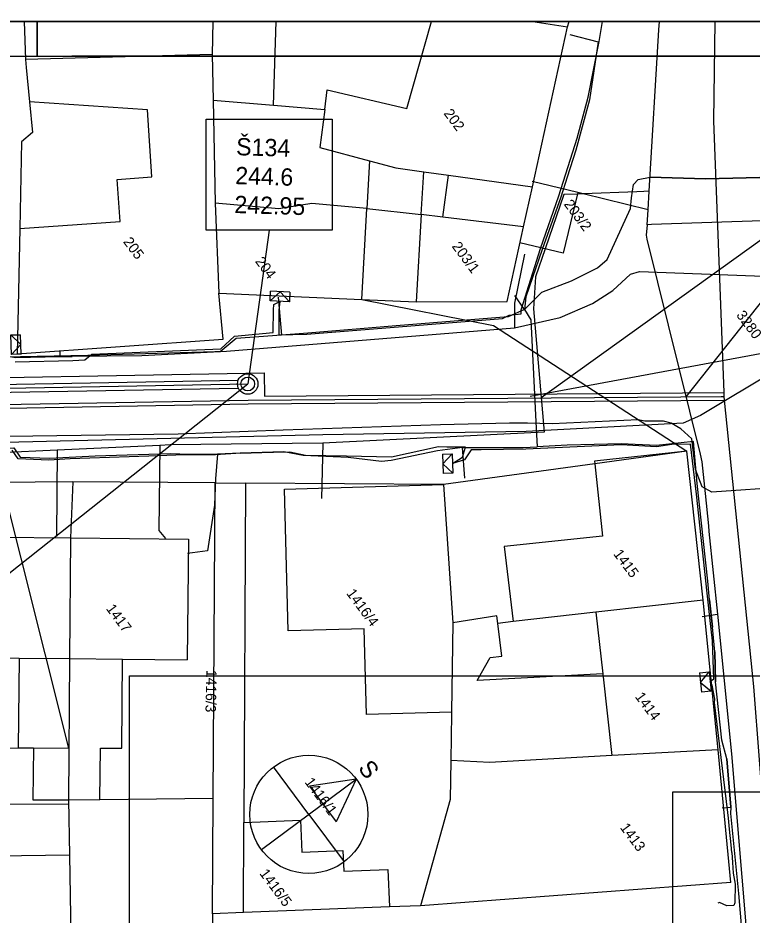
# Model space of a CAD drawing. Extents: x -601580 to 4, y -1204314 to 4.
# Drawn here: x -601370.3 to -601317.3, y -1203332.8 to -1203268.1 of the extents above; entities that cross this region are included whole.
import ezdxf

# ---------------------------------------------------------------- set-up
doc = ezdxf.new("R2010")
doc.units = 0
for name, color, linetype in [('00-EON NN', 7, 'Continuous'), ('00-EON VN', 7, 'Continuous'), ('00-INNOGY-NTL', 7, 'Continuous'), ('00-KN-HRANICE PARCEL', 7, 'Continuous'), ('00-KN-PARC. CISLA', 7, 'Continuous'), ('00-KN-VNITRNI KRESBA', 7, 'Continuous'), ('00-RAZÍTKO', 7, 'Continuous'), ('00-SITE KOM. KABEL', 7, 'Continuous'), ('00-VAK-KANAL-POTRUBI', 7, 'Continuous'), ('00-VAK-VODA-RAD IGIS', 7, 'Continuous'), ('01 KOTA', 7, 'Continuous'), ('11-REKONSTRUKCE  VYKOP', 7, 'Continuous'), ('11-REKONSTRUKCE KANALIZACE', 7, 'Continuous'), ('11-REKONSTRUKCE KANALIZACE OSA', 7, 'Continuous'), ('11-REKONSTRUKCE KANALIZACE POPIS', 7, 'Continuous'), ('11-REKONSTRUKCE VODOVOD', 7, 'Continuous'), ('11-REKONSTRUKCE VODOVOD POPIS', 7, 'Continuous'), ('Vrstva 26', 7, 'Continuous'), ('Vrstva 9', 7, 'Continuous')]:
    doc.layers.add(name, color=color, linetype=linetype)

# ---------------------------------------------------------------- blocks, each defined once
blk = doc.blocks.new('NN630')
at = {"layer": 'Vrstva 9'}
for points in [[(-3, -700), (-703, 0)], [(-703, -700), (-703, 0), (697, 0), (697, -700)], [(-3, -700), (697, 0)], [(-703, -700), (697, -700)]]:
    blk.add_lwpolyline(points, dxfattribs=at)

msp = doc.modelspace()

# ---------------------------------------------------------------- linework, layer by layer
for points in [[(-601368.935, -1203270.826), (-601368.935, -1203268.326), (-601473.985, -1203268.326), (-601473.985, -1203270.826)], [(-601368.935, -1203414.326), (-601368.935, -1203416.826), (-601263.884, -1203416.826), (-601263.884, -1203268.326), (-601368.935, -1203268.326), (-601368.935, -1203270.826)], [(-601366.435, -1203414.326), (-601266.384, -1203414.326), (-601266.384, -1203270.826), (-601366.435, -1203270.826)]]:
    msp.add_lwpolyline(points)
at = {"layer": '00-EON NN'}
for points in [[(-601370.525, -1203292.903), (-601366.381, -1203292.812), (-601365.494, -1203292.77), (-601364.997, -1203292.35), (-601355.673, -1203291.976), (-601354.686, -1203291.056), (-601351.897, -1203290.798), (-601351.885, -1203289.162), (-601351.854, -1203288.77), (-601351.434, -1203288.543), (-601351.486, -1203289.179), (-601351.498, -1203290.962), (-601349.472, -1203290.919), (-601335.35, -1203289.767), (-601334.874, -1203289.527), (-601333.996, -1203289.435), (-601334.002, -1203289.141), (-601332.604, -1203284.716), (-601331.269, -1203280.911), (-601329.955, -1203276.759), (-601329.152, -1203273.797), (-601328.355, -1203269.772), (-601328.118, -1203268.326)], [(-601320.354, -1203315.985), (-601320.091, -1203315.803), (-601320.181, -1203313.048), (-601320.343, -1203311.589), (-601320.56, -1203309.6), (-601321.326, -1203302.46), (-601321.764, -1203298.85), (-601323.127, -1203298.877), (-601324.226, -1203299.049), (-601326.763, -1203298.911), (-601333.67, -1203299.219), (-601336.88, -1203299.254)], [(-601339.353, -1203299.057), (-601339.966, -1203299.052), (-601343.369, -1203299.793), (-601346.599, -1203299.707), (-601349.562, -1203299.661), (-601350.71, -1203299.426), (-601354.23, -1203299.503), (-601356.07, -1203299.632), (-601358.929, -1203299.635), (-601360.893, -1203299.724), (-601366.566, -1203299.9), (-601368.091, -1203300.01), (-601370.311, -1203299.902), (-601370.749, -1203299.281)], [(-601336.88, -1203299.254), (-601337.616, -1203299.262), (-601338.095, -1203299.986), (-601338.956, -1203300.248), (-601338.221, -1203299.791), (-601338.009, -1203299.068), (-601339.353, -1203299.057)], [(-601320.027, -1203317.499), (-601320.012, -1203317.251), (-601320.215, -1203316.256), (-601320.354, -1203315.985)], [(-601318.779, -1203328.341), (-601318.825, -1203327.775), (-601318.942, -1203326.644), (-601319.021, -1203325.849), (-601319.078, -1203325.438), (-601320.027, -1203317.499)], [(-601318.779, -1203328.341), (-601318.726, -1203329.05), (-601318.698, -1203329.826), (-601318.544, -1203330.62), (-601318.559, -1203331.976), (-601318.639, -1203332.154), (-601319.138, -1203332.194), (-601319.667, -1203331.951), (-601319.799, -1203332)]]:
    msp.add_lwpolyline(points, dxfattribs=at)
at = {"layer": '00-EON VN'}
for points in [[(-601315.562, -1203268.326), (-601315.61, -1203274.198), (-601315.387, -1203285.467), (-601315.047, -1203290.112), (-601315.056, -1203292.512), (-601315.467, -1203293.437), (-601321.049, -1203296.77), (-601322.289, -1203297.339), (-601333.626, -1203297.94), (-601348.329, -1203298.17), (-601379.275, -1203298.932), (-601388.418, -1203299.122), (-601401.119, -1203299.449), (-601407.186, -1203299.441), (-601413.599, -1203299.611), (-601425.994, -1203301.007), (-601438.778, -1203302.641), (-601441.293, -1203303.148), (-601442.541, -1203303.128)], [(-601308.054, -1203364.739), (-601308.692, -1203358.556), (-601308.622, -1203357.458), (-601310.497, -1203339.547), (-601312.465, -1203319.363), (-601313.985, -1203302.433), (-601314.675, -1203301.923), (-601320.229, -1203302.31), (-601320.923, -1203301.928), (-601321.405, -1203300.692), (-601321.682, -1203298.456), (-601322.454, -1203297.735), (-601323.158, -1203297.323), (-601323.723, -1203297.182), (-601325.069, -1203297.198), (-601325.539, -1203297.085), (-601331.758, -1203297.38), (-601333.532, -1203297.34), (-601334.848, -1203297.345), (-601339.825, -1203297.452), (-601351.175, -1203297.832), (-601358.752, -1203298.126), (-601371.007, -1203298.293)]]:
    msp.add_lwpolyline(points, dxfattribs=at)
at = {"layer": '00-INNOGY-NTL'}
for p, q in [((-601329.907, -1203280.683), (-601333.213, -1203279.887)), ((-601367.49, -1203299.277), (-601367.557, -1203305.529)), ((-601320.927, -1203311.304), (-601319.828, -1203311.124))]:
    msp.add_line(p, q, dxfattribs=at)
for points in [[(-601324.893, -1203283.026), (-601324.829, -1203281.921), (-601324.746, -1203280.589), (-601324.05, -1203268.926), (-601324.016, -1203268.326)], [(-601329.907, -1203280.683), (-601330.969, -1203285.058), (-601334.081, -1203284.305)], [(-601325.633, -1203280.637), (-601329.527, -1203280.775), (-601329.937, -1203280.793), (-601330.922, -1203280.826), (-601332.265, -1203284.738), (-601332.959, -1203286.772), (-601333.107, -1203289.073), (-601332.331, -1203297.987)], [(-601324.829, -1203281.921), (-601329.527, -1203280.775), (-601329.907, -1203280.683)], [(-601324.746, -1203280.589), (-601325.137, -1203280.617), (-601325.633, -1203280.637)], [(-601316.599, -1203282.723), (-601324.58, -1203282.994), (-601324.893, -1203283.026), (-601324.966, -1203283.766), (-601324.924, -1203284.058), (-601321.063, -1203299.561), (-601320.961, -1203300.134), (-601320.707, -1203302.423), (-601320.48, -1203304.758), (-601320.438, -1203305.151), (-601319.828, -1203311.124), (-601318.804, -1203321.211), (-601316.942, -1203343.316)], [(-601332.331, -1203297.987), (-601348.309, -1203298.776), (-601359.342, -1203298.895), (-601360.084, -1203298.936), (-601367.49, -1203299.277), (-601371.643, -1203299.47), (-601372.283, -1203299.497), (-601387.135, -1203299.923), (-601391.708, -1203300.055), (-601393.151, -1203299.955), (-601393.463, -1203299.938), (-601394.572, -1203299.752), (-601396.304, -1203299.232), (-601396.572, -1203299.156), (-601396.715, -1203299.114), (-601406.965, -1203299.349), (-601407.169, -1203299.376), (-601414.127, -1203300.319), (-601427.425, -1203302.119), (-601427.687, -1203302.152)], [(-601360.084, -1203298.936), (-601360.159, -1203305.093), (-601359.669, -1203305.652)], [(-601348.309, -1203298.776), (-601348.423, -1203302.784)]]:
    msp.add_lwpolyline(points, dxfattribs=at)
at = {"layer": '00-KN-HRANICE PARCEL'}
for p, q in [((-601369.888, -1203268.326), (-601369.785, -1203271.067)), ((-601356.266, -1203268.326), (-601356.317, -1203270.722)), ((-601330.639, -1203268.724), (-601330.532, -1203268.326)), ((-601333.184, -1203280.277), (-601330.639, -1203268.724)), ((-601356.317, -1203270.722), (-601369.785, -1203271.067)), ((-601356.317, -1203270.722), (-601356.248, -1203274.02)), ((-601339.242, -1203279.431), (-601333.184, -1203280.277)), ((-601333.819, -1203283.164), (-601333.184, -1203280.277)), ((-601355.829, -1203287.957), (-601345.501, -1203288.398)), ((-601355.505, -1203291.278), (-601355.829, -1203287.957)), ((-601345.501, -1203288.398), (-601341.566, -1203288.566)), ((-601370.387, -1203292.336), (-601355.505, -1203291.278)), ((-601320.85, -1203310.115), (-601322.033, -1203299.361)), ((-601366.376, -1203301.564), (-601379.317, -1203301.68)), ((-601356.103, -1203301.647), (-601366.376, -1203301.564)), ((-601356.24, -1203324.415), (-601356.103, -1203301.647)), ((-601356.103, -1203301.647), (-601353.903, -1203301.658)), ((-601353.903, -1203301.658), (-601354.019, -1203326.166)), ((-601339.595, -1203301.773), (-601353.903, -1203301.658)), ((-601339.595, -1203301.773), (-601338.935, -1203311.757)), ((-601319.774, -1203320.91), (-601320.85, -1203310.115)), ((-601338.935, -1203311.757), (-601339.017, -1203318.207)), ((-601318.85, -1203330.511), (-601319.774, -1203320.91)), ((-601366.679, -1203324.529), (-601366.618, -1203328.52)), ((-601356.295, -1203332.763), (-601356.24, -1203324.415)), ((-601354.045, -1203332.674), (-601354.019, -1203326.166)), ((-601366.618, -1203328.52), (-601377.933, -1203328.711)), ((-601366.618, -1203328.52), (-601366.36, -1203342.861)), ((-601318.85, -1203330.511), (-601341.254, -1203332.172)), ((-601343.513, -1203332.266), (-601354.045, -1203332.674)), ((-601341.254, -1203332.172), (-601343.513, -1203332.266)), ((-601354.045, -1203332.674), (-601356.295, -1203332.763)), ((-601356.295, -1203332.763), (-601356.09, -1203342.1))]:
    msp.add_line(p, q, dxfattribs=at)
for points in [[(-601333.159, -1203268.326), (-601330.639, -1203268.724)], [(-601369.785, -1203271.067), (-601369.73, -1203271.661), (-601369.502, -1203274.133), (-601369.287, -1203276.352), (-601370.073, -1203277.022), (-601370.206, -1203283.285), (-601370.387, -1203292.336)], [(-601356.248, -1203274.02), (-601351.883, -1203274.38), (-601348.183, -1203274.684), (-601348.526, -1203277.443), (-601344.943, -1203278.395)], [(-601356.248, -1203274.02), (-601356.088, -1203281.449), (-601355.829, -1203287.957)], [(-601344.943, -1203278.395), (-601345.136, -1203281.826), (-601341.206, -1203282.271), (-601341.566, -1203288.566)], [(-601344.943, -1203278.395), (-601343.046, -1203278.904), (-601341.029, -1203279.188), (-601339.242, -1203279.431)], [(-601333.819, -1203283.164), (-601339.661, -1203282.457), (-601339.242, -1203279.431)], [(-601341.566, -1203288.566), (-601335.009, -1203288.556), (-601333.819, -1203283.164)], [(-601345.501, -1203288.398), (-601335.986, -1203290.277), (-601322.033, -1203299.361)], [(-601322.033, -1203299.361), (-601328.688, -1203300.278), (-601339.595, -1203301.773)], [(-601366.376, -1203301.564), (-601366.541, -1203305.622), (-601366.606, -1203314.325), (-601366.679, -1203324.529)], [(-601339.017, -1203318.207), (-601345.174, -1203318.368), (-601345.337, -1203312.175), (-601350.814, -1203312.33), (-601351.093, -1203302.088), (-601339.595, -1203301.773)], [(-601320.85, -1203310.115), (-601328.599, -1203310.984), (-601334.574, -1203311.659), (-601335.673, -1203311.789), (-601335.748, -1203311.235), (-601338.935, -1203311.757)], [(-601339.017, -1203318.207), (-601339.019, -1203318.321), (-601339.076, -1203321.7)], [(-601319.774, -1203320.91), (-601327.45, -1203321.34), (-601336.251, -1203321.832), (-601339.076, -1203321.7)], [(-601339.076, -1203321.7), (-601339.126, -1203324.502), (-601341.254, -1203332.172)], [(-601366.679, -1203324.529), (-601364.424, -1203324.512), (-601356.24, -1203324.415)], [(-601354.019, -1203326.166), (-601349.928, -1203326.006), (-601349.839, -1203328.307), (-601346.871, -1203328.196), (-601346.806, -1203329.692), (-601343.621, -1203329.57), (-601343.513, -1203332.266)]]:
    msp.add_lwpolyline(points, dxfattribs=at)
at = {"layer": '00-KN-VNITRNI KRESBA'}
for p, q in [((-601351.883, -1203274.38), (-601351.683, -1203268.326)), ((-601342.248, -1203274.626), (-601340.459, -1203268.326)), ((-601348.183, -1203274.684), (-601348.002, -1203273.267)), ((-601348.002, -1203273.267), (-601342.248, -1203274.626)), ((-601360.989, -1203274.713), (-601369.502, -1203274.133)), ((-601360.655, -1203279.559), (-601360.989, -1203274.713)), ((-601341.206, -1203282.271), (-601341.029, -1203279.188)), ((-601363.168, -1203279.73), (-601360.655, -1203279.559)), ((-601362.955, -1203282.785), (-601363.168, -1203279.73)), ((-601351.502, -1203281.856), (-601356.088, -1203281.449)), ((-601349.117, -1203281.48), (-601351.502, -1203281.856)), ((-601345.136, -1203281.826), (-601349.117, -1203281.48)), ((-601345.501, -1203288.398), (-601345.136, -1203281.826)), ((-601339.661, -1203282.457), (-601341.206, -1203282.271)), ((-601370.206, -1203283.285), (-601362.955, -1203282.785)), ((-601322.033, -1203299.361), (-601328.709, -1203300.082)), ((-601328.709, -1203300.082), (-601328.688, -1203300.278)), ((-601328.688, -1203300.278), (-601328.116, -1203305.495)), ((-601375.028, -1203305.546), (-601366.541, -1203305.622)), ((-601366.541, -1203305.622), (-601358.025, -1203305.702)), ((-601358.025, -1203305.702), (-601358.106, -1203314.418)), ((-601328.116, -1203305.495), (-601335.217, -1203306.245)), ((-601335.217, -1203306.245), (-601334.574, -1203311.659)), ((-601328.599, -1203310.984), (-601328.105, -1203315.425)), ((-601335.387, -1203314.155), (-601335.673, -1203311.789)), ((-601375.1, -1203314.241), (-601370.254, -1203314.293)), ((-601370.254, -1203314.293), (-601370.318, -1203320.767)), ((-601370.254, -1203314.293), (-601366.606, -1203314.325)), ((-601366.606, -1203314.325), (-601362.774, -1203314.371)), ((-601362.838, -1203320.794), (-601362.774, -1203314.371)), ((-601362.774, -1203314.371), (-601358.106, -1203314.418)), ((-601337.175, -1203315.906), (-601336.239, -1203314.264)), ((-601336.239, -1203314.264), (-601335.387, -1203314.155)), ((-601328.105, -1203315.425), (-601337.175, -1203315.906)), ((-601328.105, -1203315.425), (-601327.45, -1203321.34)), ((-601370.318, -1203320.767), (-601369.218, -1203320.773)), ((-601369.218, -1203320.773), (-601369.261, -1203324.54)), ((-601364.424, -1203324.512), (-601364.384, -1203320.809)), ((-601364.384, -1203320.809), (-601362.838, -1203320.794)), ((-601369.261, -1203324.54), (-601366.679, -1203324.529))]:
    msp.add_line(p, q, dxfattribs=at)
at = {"layer": '00-RAZÍTKO'}
for points in [[(-601579.036, -1203268.326), (-601263.884, -1203268.326), (-601263.884, -1203416.826), (-601579.036, -1203416.826)], [(-601576.536, -1203270.826), (-601266.384, -1203270.826), (-601266.384, -1203414.326), (-601576.536, -1203414.326)], [(-601266.384, -1203414.326), (-601362.277, -1203414.326), (-601362.277, -1203315.575), (-601266.384, -1203315.575)], [(-601323.044, -1203323.964), (-601269.935, -1203323.964), (-601269.935, -1203360.386), (-601323.044, -1203360.386)]]:
    msp.add_lwpolyline(points, close=True, dxfattribs=at)
at = {"layer": '00-SITE KOM. KABEL'}
for points in [[(-601465.666, -1203268.077), (-601465.45, -1203271.476), (-601465.203, -1203281.741), (-601464.718, -1203292.278), (-601464.228, -1203298.054), (-601463.764, -1203299.317), (-601461.865, -1203300.198), (-601444.628, -1203297.566), (-601422.377, -1203294.288), (-601417.815, -1203293.891), (-601412.74, -1203293.648), (-601407.783, -1203293.531), (-601395.711, -1203293.151), (-601385.448, -1203292.968), (-601371.384, -1203292.553), (-601365.297, -1203292.432), (-601355.273, -1203292.127), (-601334.483, -1203290.457)], [(-601330.47, -1203269.27), (-601328.426, -1203269.809)], [(-601328.426, -1203269.809), (-601329.065, -1203273.981), (-601330.041, -1203277.633), (-601330.679, -1203279.575), (-601331.12, -1203281.011), (-601332.487, -1203284.791), (-601333.664, -1203288.205), (-601333.756, -1203289.12)], [(-601328.426, -1203269.809), (-601329.065, -1203273.981)], [(-601326.04, -1203281.077), (-601325.887, -1203280.091), (-601325.55, -1203279.741), (-601324.673, -1203279.563), (-601320.689, -1203279.695), (-601315.769, -1203279.58), (-601314.58, -1203279.369)], [(-601330.679, -1203279.575), (-601331.12, -1203281.011)], [(-601315.769, -1203279.58), (-601320.689, -1203279.695), (-601324.673, -1203279.563)], [(-601333.756, -1203289.12), (-601332.514, -1203287.874), (-601330.35, -1203287.065), (-601328.481, -1203286.126), (-601327.79, -1203285.514), (-601326.104, -1203281.846), (-601326.04, -1203281.077)], [(-601331.12, -1203281.011), (-601332.487, -1203284.791)], [(-601333.744, -1203285.126), (-601334.476, -1203288.671), (-601334.483, -1203290.457)], [(-601334.483, -1203290.457), (-601331.169, -1203289.703), (-601328.84, -1203288.697), (-601327.365, -1203287.764), (-601326.09, -1203286.58), (-601325.455, -1203286.396), (-601315.864, -1203286.749), (-601314.56, -1203287.064), (-601314.128, -1203296.37), (-601313.734, -1203301.632), (-601312.864, -1203310.924), (-601312.114, -1203318.998), (-601311.17, -1203328.659), (-601309.968, -1203341.453), (-601308.728, -1203353.895), (-601308.139, -1203359.386), (-601306.411, -1203376.361), (-601306.539, -1203379.881), (-601303.995, -1203380.271)], [(-601351.532, -1203288.242), (-601351.302, -1203290.985)], [(-601333.756, -1203289.12), (-601334.451, -1203288.117)], [(-601333.756, -1203289.12), (-601334.937, -1203289.66), (-601343.032, -1203290.314), (-601349.399, -1203290.831), (-601351.302, -1203290.985)], [(-601333.756, -1203289.12), (-601333.288, -1203289.869), (-601332.921, -1203297.729), (-601332.852, -1203299.047)], [(-601334.937, -1203289.66), (-601343.032, -1203290.314)], [(-601333.288, -1203289.869), (-601332.921, -1203297.729)], [(-601351.302, -1203290.985), (-601354.581, -1203291.215), (-601355.726, -1203292.189), (-601361.399, -1203292.465), (-601366.42, -1203292.53), (-601367.304, -1203292.514)], [(-601349.399, -1203290.831), (-601351.302, -1203290.985)], [(-601367.316, -1203292.162), (-601367.304, -1203292.514)], [(-601371.229, -1203292.476), (-601370.496, -1203292.592), (-601367.304, -1203292.514)], [(-601370.496, -1203292.592), (-601367.304, -1203292.514), (-601366.42, -1203292.53)], [(-601324.215, -1203298.938), (-601326.784, -1203298.815), (-601330.669, -1203298.934), (-601332.852, -1203299.047)], [(-601318.845, -1203325.065), (-601319.151, -1203321.581), (-601319.495, -1203320.23), (-601319.956, -1203316.001), (-601320.001, -1203313.843), (-601320.168, -1203312.074), (-601320.388, -1203310.083), (-601320.52, -1203308.748), (-601321.282, -1203301.68), (-601321.541, -1203298.647), (-601324.215, -1203298.938)], [(-601373.167, -1203299.245), (-601370.624, -1203299.113), (-601370.182, -1203299.794), (-601368.032, -1203299.854), (-601364.749, -1203299.697), (-601359.348, -1203299.523), (-601357.926, -1203299.576), (-601355.924, -1203299.572)], [(-601355.924, -1203299.572), (-601356.073, -1203301.352), (-601356.133, -1203303.251), (-601356.635, -1203306.551), (-601358.08, -1203306.752)], [(-601343.385, -1203300.041), (-601344.079, -1203300.095), (-601346.49, -1203299.817), (-601349.749, -1203299.671), (-601351.137, -1203299.394), (-601354.278, -1203299.509), (-601355.924, -1203299.572)], [(-601354.278, -1203299.509), (-601351.137, -1203299.394)], [(-601338.226, -1203299.088), (-601340.027, -1203299.329), (-601343.385, -1203300.041)], [(-601338.226, -1203299.088), (-601333.86, -1203299.098), (-601332.852, -1203299.047)], [(-601338.055, -1203301.315), (-601338.226, -1203299.088)], [(-601320.388, -1203310.083), (-601320.168, -1203312.074)], [(-601320.001, -1203313.843), (-601319.956, -1203316.001)], [(-601319.151, -1203321.581), (-601318.845, -1203325.065), (-601318.869, -1203325.519)], [(-601319.481, -1203325.114), (-601318.845, -1203325.065)], [(-601318.845, -1203325.065), (-601318.869, -1203325.519), (-601318.313, -1203331.284), (-601317.965, -1203335.259)]]:
    msp.add_lwpolyline(points, dxfattribs=at)
at = {"layer": '00-VAK-KANAL-POTRUBI'}
msp.add_circle((-601353.74, -1203294.504), 0.5, dxfattribs=at)
at = {"layer": '00-VAK-VODA-RAD IGIS'}
for points in [[(-601319.347, -1203295.118), (-601320.074, -1203275.51), (-601319.987, -1203268.326)], [(-601319.336, -1203295.401), (-601319.554, -1203295.424)], [(-601319.336, -1203295.401), (-601319.347, -1203295.118)], [(-601319.308, -1203295.668), (-601319.336, -1203295.401)], [(-601310.964, -1203387.736), (-601311.494, -1203381.296), (-601313.764, -1203356.052), (-601316.384, -1203326.926), (-601317.183, -1203316.351), (-601319.308, -1203295.668)]]:
    msp.add_lwpolyline(points, dxfattribs=at)
at = {"layer": '01 KOTA'}
for p, q in [((-601349.328, -1203325.58), (-601351.873, -1203322.152)), ((-601349.328, -1203325.58), (-601351.873, -1203322.152)), ((-601352.756, -1203328.124), (-601345.9, -1203323.035)), ((-601352.756, -1203328.124), (-601345.9, -1203323.035)), ((-601345.9, -1203323.035), (-601349.282, -1203323.544)), ((-601345.9, -1203323.035), (-601349.282, -1203323.544)), ((-601349.282, -1203323.544), (-601347.366, -1203326.125)), ((-601349.282, -1203323.544), (-601347.366, -1203326.125)), ((-601345.9, -1203323.035), (-601347.366, -1203326.125)), ((-601345.9, -1203323.035), (-601347.366, -1203326.125)), ((-601349.328, -1203325.58), (-601346.784, -1203329.008)), ((-601349.328, -1203325.58), (-601346.784, -1203329.008))]:
    msp.add_line(p, q, dxfattribs=at)
msp.add_circle((-601349.328, -1203325.58), 4.269, dxfattribs=at)
msp.add_circle((-601349.328, -1203325.58), 4.269, dxfattribs=at)
at = {"layer": '11-REKONSTRUKCE  VYKOP'}
msp.add_line((-601352.554, -1203293.702), (-601352.531, -1203295.374), dxfattribs=at)
for points in [[(-601536.909, -1203306.471), (-601527.537, -1203305.806), (-601496.057, -1203307.883), (-601450.147, -1203301.951), (-601411.254, -1203294.759), (-601352.554, -1203293.702)], [(-601353.717, -1203295.944), (-601319.334, -1203295.681)], [(-601352.531, -1203295.374), (-601319.338, -1203295.121)], [(-601521.772, -1203308.411), (-601495.987, -1203310.113), (-601449.803, -1203304.145), (-601411.03, -1203296.976), (-601353.714, -1203295.944)]]:
    msp.add_lwpolyline(points, dxfattribs=at)
at = {"layer": '11-REKONSTRUKCE KANALIZACE'}
msp.add_line((-601352.189, -1203283.411), (-601353.74, -1203294.504), dxfattribs=at)
for points in [[(-601410.495, -1203295.246), (-601354.43, -1203294.236)], [(-601354.159, -1203294.231), (-601354.159, -1203294.231)], [(-601410.485, -1203295.806), (-601354.42, -1203294.796)], [(-601354.149, -1203294.791), (-601354.149, -1203294.791)]]:
    msp.add_lwpolyline(points, dxfattribs=at)
for radius in [0.74, 0.5, 0.5]:
    msp.add_circle((-601353.74, -1203294.504), radius, dxfattribs=at)
at = {"layer": '11-REKONSTRUKCE KANALIZACE OSA'}
msp.add_lwpolyline([(-601536.854, -1203307.249), (-601527.535, -1203306.588), (-601496.033, -1203308.666), (-601450.026, -1203302.722), (-601411.175, -1203295.538), (-601353.74, -1203294.504)], dxfattribs=at)
at = {"layer": '11-REKONSTRUKCE KANALIZACE POPIS'}
for p, q in [((-601373.928, -1203310.497), (-601353.74, -1203294.504)), ((-601366.652, -1203320.798), (-601373.173, -1203294.909))]:
    msp.add_line(p, q, dxfattribs=at)
for points in [[(-601356.742, -1203275.393), (-601347.637, -1203275.393), (-601347.637, -1203283.411), (-601356.742, -1203283.411)], [(-601356.742, -1203275.393), (-601347.637, -1203275.393), (-601347.637, -1203283.411), (-601356.742, -1203283.411)], [(-601402.974, -1203320.708), (-601366.652, -1203320.798), (-601366.674, -1203324.853), (-601402.974, -1203325.043)]]:
    msp.add_lwpolyline(points, close=True, dxfattribs=at)
at = {"layer": '11-REKONSTRUKCE VODOVOD'}
for points in [[(-601520.956, -1203308.185), (-601495.996, -1203309.831), (-601449.846, -1203303.869), (-601411.058, -1203296.696), (-601353.719, -1203295.664)], [(-601353.719, -1203295.664), (-601319.336, -1203295.401)]]:
    msp.add_lwpolyline(points, dxfattribs=at)
at = {"layer": '11-REKONSTRUKCE VODOVOD POPIS'}
for p, q in [((-601308.431, -1203278.17), (-601332.547, -1203295.502)), ((-601308.431, -1203278.17), (-601322.094, -1203295.422)), ((-601305.98, -1203290.316), (-601333.342, -1203295.417))]:
    msp.add_line(p, q, dxfattribs=at)

# ---------------------------------------------------------------- block references
at = {"layer": 'Vrstva 26'}
for p, xscale, yscale, rotation in [((-601351.433, -1203288.543), 0.0010000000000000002, 0.0010000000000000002, 177.42102930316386), ((-601370.823, -1203291.665), 0.001, 0.001, 91.56774602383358), ((-601338.956, -1203300.248), 0.000999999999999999, 0.0009999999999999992, -88.17682620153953), ((-601320.354, -1203315.985), 0.001, 0.001, -84.05009922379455)]:
    msp.add_blockref('NN630', p, dxfattribs=dict(at, xscale=xscale, yscale=yscale, rotation=rotation))

# ---------------------------------------------------------------- texts
msp.add_text('S', height=1.241, rotation=306.58532).set_placement((-601345.818, -1203322.249))
msp.add_text('S', height=1.241, rotation=306.58532).set_placement((-601345.818, -1203322.249))
at = {"layer": '00-KN-PARC. CISLA'}
for s, rotation, p in [('202', 306.58532, (-601339.622, -1203274.976)), ('203/2', 306.58532, (-601330.947, -1203281.53)), ('205', 306.58532, (-601362.769, -1203284.242)), ('203/1', 306.58532, (-601339.039, -1203284.569)), ('204', 306.58532, (-601353.239, -1203285.657)), ('3280', 306.58532, (-601318.498, -1203289.54)), ('1415', 306.58532, (-601327.373, -1203306.78)), ('1416/4', 306.58532, (-601346.655, -1203309.628)), ('1417', 306.58532, (-601364.005, -1203310.732)), ('1416/3', 268.58532, (-601356.721, -1203315.144)), ('1414', 306.58532, (-601325.81, -1203317.09)), ('1416/1', 306.58532, (-601349.664, -1203323.258)), ('1413', 306.58532, (-601326.893, -1203326.537)), ('1416/5', 306.58532, (-601352.927, -1203329.851))]:
    msp.add_text(s, height=0.75, rotation=rotation, dxfattribs=at).set_placement(p)
at = {"layer": '11-REKONSTRUKCE KANALIZACE POPIS'}
for s, p in [('Š134', (-601354.592, -1203277.986)), ('244.6', (-601354.655, -1203280.073)), ('242.95', (-601354.718, -1203282.16))]:
    msp.add_text(s, height=1.25, rotation=358.2688, dxfattribs=at).set_placement(p)

doc.saveas('drawing.dxf')
